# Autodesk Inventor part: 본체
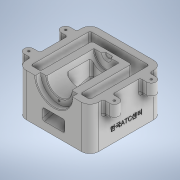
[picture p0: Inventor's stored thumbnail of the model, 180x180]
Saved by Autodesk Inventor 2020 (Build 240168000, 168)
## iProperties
Created: 2022-03
Part Number: 본체
Material: 일반
Document SubType Name: Modeling
Designer: Administrator
Density: 1 g/cm^3
Appearance: 기본값
Author: Administrator
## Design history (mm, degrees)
sketch "스케치1"
  geometry: L1 (-55, 55)-(55, 55); L2 (55, 55)-(55, -55); L3 (55, -55)-(-55, -55); L4 (-55, -55)-(-55, 55); L5 (-55, 55)-(55, -55); L6 (55, 55)-(-55, -55); L7 (45, 45)-(-45, 45); L8 (-45, 45)-(-45, -45); L9 (-45, -45)-(45, -45); L10 (45, -45)-(45, 45); 1 further point
  constraints: 20 end point, 4 parallel, 2 midpoint, 2 perpendicular, 1 horizontal, 3 other
  dimensions: "d0" = 110 distance of L1.start L1.end; "d1" = 110 distance of L3.end L1.start; "d2" = 10 distance between parallel lines of L1 L7
extrude "돌출1" new body sketch "스케치1" distance "d3" = 65; taper "d4" = 0 deg
sketch "스케치2"
  geometry: L1 (-65, 28)-(65, 28); L2 (55, 55)-(-55, 55) reference; L3 (-65, -28)-(65, -28); L4 (-65, 35)-(-53.105, 35); L5 (-65, 21)-(-53.105, 21); L6 (-53.105, 21)-(-53.105, 35); L7 (-65, -21)-(-51.736, -21); L8 (-51.736, -21)-(-51.736, -35); L9 (-51.736, -35)-(-65, -35); L10 (65, 35)-(51.257, 35); L11 (65, 21)-(51.91, 21); L12 (51.91, 21)-(51.257, 35); L13 (65, -35)-(52.819, -35); L14 (65, -21)-(51.257, -21); L15 (51.257, -21)-(52.819, -35); A1 r 7 centre (-65, 28) between (-65, 35) and (-65, 21); A2 r 7 centre (65, 28) between (65, 21) and (65, 35); A3 r 7 centre (-65, -28) between (-65, -21) and (-65, -35); A4 r 7 centre (65, -28) between (65, -35) and (65, -21); 5 further points
  constraints: 28 end point, 9 horizontal, 8 point on circle, 4 centre point, 4 midpoint, 4 tangent, 4 vertical alignment, 2 perpendicular, 1 horizontal alignment, 1 vertical
  dimensions: "d5" = 14 diameter of A1; "d6" = 14 diameter of A2; "d7" = 130 distance of L1.end L1.start; "d8" = 14 diameter of A4; "d9" = 14 diameter of A3; "d10" = 130 distance of L3.end L3.start; "d12" = 27 distance from line of L1.start L2; "d13" = 56 distance of L3.start L1.start
extrude "돌출2" join sketch "스케치2" distance "d14" = 20; taper "d15" = 0 deg
sketch "스케치3"
  geometry: L1 (0, 65)-(110, 65) reference; L2 (0, 0)-(110, 0) reference; A1 r 30 centre (55, 65) between (25, 65) and (85, 65); 3 further points
  constraints: 2 midpoint, 2 point on circle, 2 point on line, 1 centre point, 1 coincident, 1 vertical alignment
  dimensions: "d16" = 60 diameter of A1
extrude "돌출3" join sketch "스케치3" distance "d17" = 88; taper "d18" = 0 deg
sketch "스케치4"
  geometry: L1 (0, 0)-(110, 0) reference; L2 (0, 65)-(110, 65) reference; A1 r 19 centre (55, 65) between (36, 65) and (74, 65); 2 further points
  constraints: 2 midpoint, 2 point on circle, 2 point on line, 1 centre point, 1 vertical alignment
  dimensions: "d19" = 38 diameter of A1
extrude "돌출4" cut sketch "스케치4" distance "d20" = 80; taper "d21" = 0 deg
sketch "스케치5"
  geometry: L1 (0, 0)-(110, 0) reference; L2 (36, 65)-(74, 65) reference; C1 r 28 at (55, 65); A1 r 19 centre (55, 65) between (36, 65) and (74, 65) reference; 2 further points
  constraints: 1 centre point, 1 coincident, 1 midpoint, 1 vertical alignment
  dimensions: "d22" = 56 diameter of C1
extrude "돌출5" cut sketch "스케치5" distance "d23" = 8; taper "d24" = 0 deg
sketch "스케치6"
  geometry: L1 (-19, 25)-(19, 25) reference; L2 (-7.5, 25)-(-5.191, 29); L3 (-5.191, 29)-(0, 29); L4 (0, 0)-(0, 43.388); 1 further point
  constraints: 6 end point, 2 point on line, 1 horizontal, 1 vertical
  dimensions: "d25" = 15 diameter of L2.start L4; "d27" = 30 deg angle of L4 L2; "d28" = 4 distance between parallel lines of L1 L3
revolve "회전1" sketch "스케치6" stored, may be unused: angle "d29" = 90 deg
fillet "모깎기1" dims "d30" = 1
node "스케치7"
chamfer "모따기1" distance "d31" = 1; stored, may be unused: second distance "d32" = 2, angle "d33" = 45 deg
sketch "스케치9"
  geometry: L1 (33, 35)-(33, 65) reference; L2 (-45, 0)-(-45, 65) reference; L3 (33, 30)-(-45, 9.1); L4 (-45, 35)-(33, 35) reference; L5 (33, 30)-(33, 44.666); L6 (33, 44.666)-(-45, 44.666); L7 (-45, 65)-(-45, 35) reference; 1 further point
  constraints: 6 end point, 5 point on line, 1 perpendicular
  dimensions: "d34" = 5 distance of L1.start L3.start
extrude "돌출6" join sketch "스케치9" stored distance "d36" = 60; taper "d37" = 0 deg
sketch "스케치10"
  geometry: L1 (0, 0)-(0, 78) reference; L2 (0, 0)-(0, 78) reference; L3 (7.942, 0)-(0, 0) reference; L4 (7.942, 78)-(7.942, 0) reference; L5 (7.942, 78)-(0, 78) reference; L6 (0, 0)-(7.942, 0) reference; L7 (0, 78)-(0, 0); L8 (7.942, 0)-(0, 0) reference; L9 (0, 0)-(7.942, 0); L10 (7.942, 78)-(7.942, 0) reference; L11 (7.942, 0)-(7.942, 78); L12 (7.942, 78)-(0, 78); 3 further points
  constraints: 8 end point, 3 perpendicular, 1 collinear
extrude "돌출7" join sketch "스케치10" stored distance "d38" = 60; taper "d39" = 0 deg
sketch "스케치11"
  geometry: L1 (7.942, 0)-(7.942, -78) reference; L2 (7.942, 0)-(0, 0) reference; L3 (0, -78)-(0, 0) reference; L4 (7.942, -78)-(0, -78) reference; 1 further point
extrude "돌출8" join sketch "스케치11" stored distance "d40" = 60; taper "d41" = 0 deg
sketch "스케치12"
  geometry: L1 (-45, 9.1)-(33, 30) reference; L2 (-55, 11.597)-(19, 31.425); L3 (-55, 0)-(-55, 65) reference; L4 (-46, 46)-(24, 46) reference; L5 (19, 31.425)-(19, 57.378); L6 (19, 57.378)-(-19, 57.378); L7 (-19, 57.378)-(-19, 38.843); L8 (-19, 34.622)-(19, 57.378); L9 (19, 34.622)-(-19, 57.378); L10 (-47, 65)-(-47, 45) reference; L11 (-55, 29.197)-(-19, 38.843); L12 (-45, 0)-(45, 0) reference; 3 further points
  constraints: 14 end point, 4 point on line, 3 midpoint, 3 parallel
  dimensions: "d44" = 38 distance of L5.end L6.end; "d46" = 36 distance between parallel lines of L3 L7; "d47" = 17 distance between parallel lines of L2 L11; "d80" = 5 distance between parallel lines of L1 L2
extrude "돌출9" cut sketch "스케치12" stored distance "d48" = 34; taper "d49" = 0 deg
fillet "모깎기2" dims "d50" = 13
fillet "모깎기3" dims "d51" = 3
fillet "모깎기4" dims "d52" = 3
fillet "모깎기5" dims "d53" = 3
fillet "모깎기6" dims "d54" = 3
fillet "모깎기7" dims "d55" = 3
fillet "모깎기8" dims "d56" = 3
fillet "모깎기9" dims "d57" = 3
fillet "모깎기10" dims "d58" = 2.9
fillet "모깎기11" dims "d59" = 3
sketch "스케치13" dims "d60" = 46
  geometry: L1 (28, 65)-(82, 65) reference; 3 further points
  constraints: 2 vertical alignment, 1 midpoint, 2 other
hole "구멍1" sketch "스케치13" at (55, 42) diameter "d61" = 3.242; stored, may be unused: countersink angle "d65" = 60 deg, drill point angle "d67" = 118 deg; dims "d62" = 9, "d63" = 4.25, "d64" = 2, "d66" = 11
sketch "스케치14"
  geometry: A1 r 7 centre (-65, 28) between (-65, 35) and (-65, 21) reference; A2 r 7 centre (-65, -28) between (-65, -21) and (-65, -35) reference; A3 r 7 centre (65, 28) between (65, 21) and (65, 35) reference; A4 r 7 centre (65, -28) between (65, -35) and (65, -21) reference; A5 r 4 centre (65, -28) between (65, -32) and (65, -24) reference; 5 further points
  constraints: 4 coincident
hole "구멍2" sketch "스케치14" at (65, 28), (65, -28), (-65, -28), (-65, 28) diameter "d68" = 3.242; stored, may be unused: countersink angle "d72" = 60 deg, drill point angle "d74" = 118 deg; dims "d69" = 9, "d70" = 4.25, "d71" = 2, "d73" = 11
sketch "스케치15"
  geometry: L1 (-65, -13)-(0, -13) reference; 2 further points
  constraints: 1 other
  dimensions: "d75" = 55 distance from line of L1 point (-20, 42); "d76" = 20 distance of point (0, 42) point (-20, 42)
feature "엠보싱1" sketch "스케치15" dims "d0" = 110, "d1" = 110, "d2" = 10, "d5" = 14, "d6" = 14, "d7" = 130, "d8" = 14, "d9" = 14, "d10" = 130, "d12" = 27, "d13" = 56, "d77" = 0.5, "d78" = 0
node "솔리드1"
node "투영된 루프1"
node "투영된 루프2"
feature "A9D066F2-1C7D-4E18-AEED-F7BC21143FA4" dims "d68" = 3.242, "d69" = 9, "d70" = 4.25, "d71" = 2, "d72" = 60 deg, "d73" = 11, "d74" = 118 deg
other parameters: "d43" = 17
